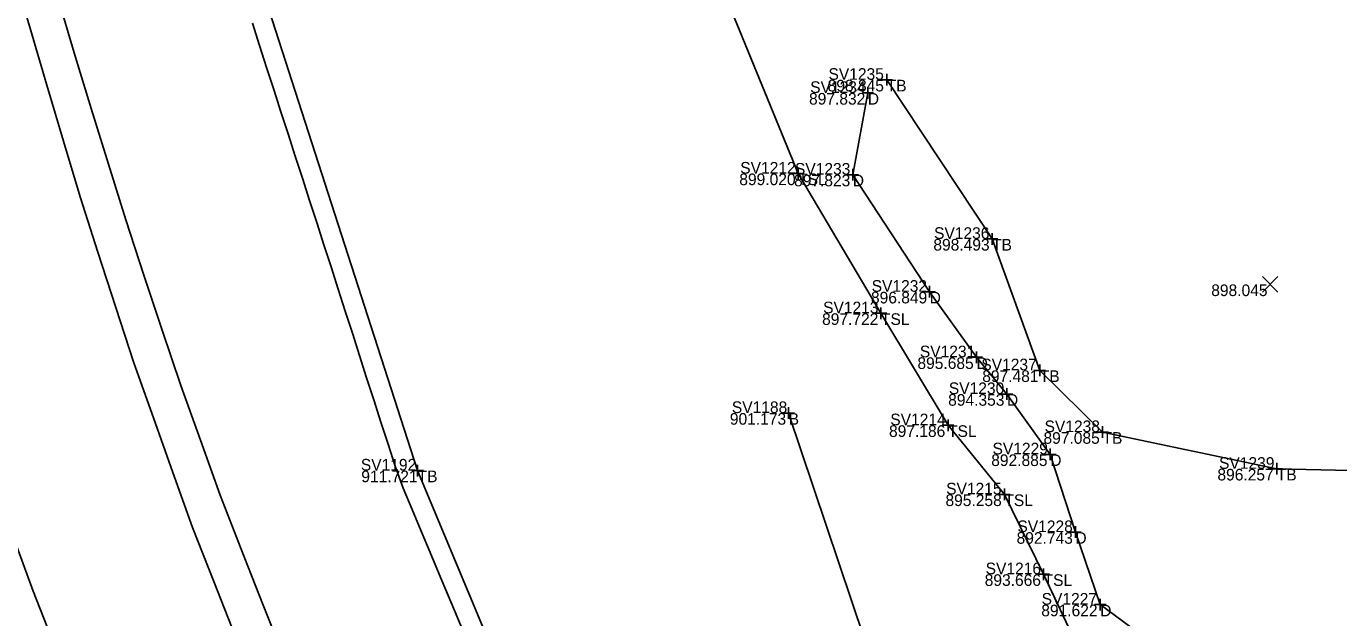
# Model space of a CAD drawing. Extents: x 1918148 to 1919797, y 624701 to 627089.
# Drawn here: x 1918934.8 to 1919047.5, y 625655.4 to 625706.2 of the extents above; entities that cross this region are included whole.
import ezdxf

# ---------------------------------------------------------------- set-up
doc = ezdxf.new("R2010")
doc.units = 0
for name, color, linetype in [('DR_X_Ditch', 7, 'Continuous'), ('PM_X_Edge_Line', 7, 'Continuous'), ('PV_X_Shoulder_Aggregate', 7, 'Continuous'), ('RD_X_Concrete_Pad', 7, 'Continuous'), ('SV_X_Break_Lines', 7, 'Continuous'), ('SV_X_Random_Point', 7, 'Continuous'), ('SV_X_Shot_Marker', 7, 'Continuous'), ('SV_X_Text_Comment', 7, 'Continuous'), ('SV_X_Text_Elevation', 7, 'Continuous'), ('SV_X_Text_Name', 7, 'Continuous'), ('SV_X_Toe_of_Slope', 7, 'Continuous'), ('SV_X_Top_of_Bank', 7, 'Continuous')]:
    doc.layers.add(name, color=color, linetype=linetype)

msp = doc.modelspace()

# ---------------------------------------------------------------- linework, layer by layer
at = {"layer": 'DR_X_Ditch'}
msp.add_lwpolyline([(1919035.48, 625645.33), (1919035.51, 625646.58), (1919031.08, 625653.51), (1919027.02, 625656.51), (1919024.89, 625662.74), (1919022.73, 625669.42), (1919019.01, 625674.6), (1919016.4, 625677.76), (1919012.37, 625683.39), (1919005.77, 625693.45), (1919007.06, 625700.47)], dxfattribs=at)
at = {"layer": 'PM_X_Edge_Line'}
for points in [[(1918933.7, 625710.72), (1918935.12, 625705.92), (1918936.55, 625701.13), (1918937.97, 625696.34), (1918939.4, 625691.55), (1918940.93, 625686.79), (1918942.47, 625682.03), (1918944.02, 625677.28), (1918945.69, 625672.56), (1918947.36, 625667.85), (1918949.05, 625663.15), (1918950.88, 625658.49), (1918952.72, 625653.84)], [(1918933.64, 625662.36), (1918935.37, 625657.67), (1918937.2, 625653.01), (1918939.04, 625648.36), (1918940.88, 625643.72), (1918942.86, 625639.13), (1918944.84, 625634.53), (1918946.83, 625629.94), (1918948.9, 625625.39), (1918950.97, 625620.84), (1918953.05, 625616.3), (1918955.27, 625611.81), (1918957.48, 625607.33), (1918959.71, 625602.86), (1918962.15, 625598.49), (1918964.6, 625594.13), (1918967.05, 625589.77), (1918969.6, 625585.47), (1918972.15, 625581.17)]]:
    msp.add_lwpolyline(points, dxfattribs=at)
at = {"layer": 'PV_X_Shoulder_Aggregate'}
msp.add_lwpolyline([(1918954.19, 625706.47), (1918954.81, 625704.56), (1918955.42, 625702.66), (1918956.04, 625700.76), (1918956.65, 625698.85), (1918957.26, 625696.95), (1918957.88, 625695.05), (1918958.49, 625693.14), (1918959.1, 625691.24), (1918959.72, 625689.33), (1918960.33, 625687.43), (1918960.95, 625685.53), (1918961.56, 625683.62), (1918962.17, 625681.72), (1918962.79, 625679.82), (1918963.4, 625677.91), (1918964.01, 625676.01), (1918964.63, 625674.11), (1918965.24, 625672.2), (1918965.86, 625670.3), (1918966.47, 625668.4), (1918967.16, 625666.52), (1918967.93, 625664.68), (1918968.7, 625662.83), (1918969.47, 625660.98), (1918970.24, 625659.14), (1918971.01, 625657.29), (1918971.78, 625655.45), (1918972.55, 625653.6)], dxfattribs=at)
at = {"layer": 'RD_X_Concrete_Pad'}
msp.add_lwpolyline([(1918937.48, 625708.71), (1918938.89, 625703.91), (1918940.35, 625699.13), (1918941.82, 625694.35), (1918943.32, 625689.58), (1918944.88, 625684.83), (1918946.44, 625680.08), (1918948.06, 625675.35), (1918949.74, 625670.64), (1918951.43, 625665.93), (1918953.22, 625661.27), (1918955.07, 625656.62), (1918956.92, 625651.98)], dxfattribs=at)
at = {"layer": 'SV_X_Break_Lines'}
msp.add_lwpolyline([(1919206.86, 625400.05), (1919170.29, 625439.2), (1919138.05, 625478.01), (1919112.93, 625508.78), (1919087.56, 625546), (1919063.33, 625584.96), (1919048.27, 625604.54), (1919031.79, 625617.49), (1919020.42, 625620.88), (1919013.82, 625627.54), (1919010.2, 625639.42), (1919006.75, 625653.62), (1919000.26, 625672.97)], dxfattribs=at)
at = {"layer": 'SV_X_Random_Point'}
for p, q in [((1919040.96, 625683.35), (1919042.29, 625684.69)), ((1919040.96, 625684.69), (1919042.29, 625683.35))]:
    msp.add_line(p, q, dxfattribs=at)
at = {"layer": 'SV_X_Shot_Marker'}
for p, q in [((1919008.68, 625702.1), (1919008.68, 625701.1)), ((1919007.06, 625700.97), (1919007.06, 625699.97)), ((1919008.18, 625701.6), (1919009.18, 625701.6)), ((1919008.68, 625701.6), (1919008.68, 625701.6)), ((1919006.56, 625700.47), (1919007.56, 625700.47)), ((1919007.06, 625700.47), (1919007.06, 625700.47)), ((1919001.08, 625694.04), (1919001.08, 625693.04)), ((1919005.77, 625693.95), (1919005.77, 625692.95)), ((1919000.58, 625693.54), (1919001.58, 625693.54)), ((1919001.08, 625693.54), (1919001.08, 625693.54)), ((1919005.27, 625693.45), (1919006.27, 625693.45)), ((1919005.77, 625693.45), (1919005.77, 625693.45)), ((1919017.73, 625688.43), (1919017.73, 625687.43)), ((1919017.23, 625687.93), (1919018.23, 625687.93)), ((1919017.73, 625687.93), (1919017.73, 625687.93)), ((1919012.37, 625683.89), (1919012.37, 625682.89)), ((1919011.87, 625683.39), (1919012.87, 625683.39)), ((1919012.37, 625683.39), (1919012.37, 625683.39)), ((1919007.69, 625681.54), (1919008.69, 625681.54)), ((1919008.19, 625682.04), (1919008.19, 625681.04)), ((1919008.19, 625681.54), (1919008.19, 625681.54)), ((1919016.4, 625678.26), (1919016.4, 625677.26)), ((1919015.9, 625677.76), (1919016.9, 625677.76)), ((1919016.4, 625677.76), (1919016.4, 625677.76)), ((1919021.83, 625677.14), (1919021.83, 625676.14)), ((1919021.33, 625676.64), (1919022.33, 625676.64)), ((1919021.83, 625676.64), (1919021.83, 625676.64)), ((1919019.01, 625675.1), (1919019.01, 625674.1)), ((1919018.51, 625674.6), (1919019.51, 625674.6)), ((1919019.01, 625674.6), (1919019.01, 625674.6)), ((1918999.76, 625672.97), (1919000.76, 625672.97)), ((1919000.26, 625673.47), (1919000.26, 625672.47)), ((1919000.26, 625672.97), (1919000.26, 625672.97)), ((1919013.45, 625671.92), (1919014.45, 625671.92)), ((1919013.95, 625672.42), (1919013.95, 625671.42)), ((1919013.95, 625671.92), (1919013.95, 625671.92)), ((1919027.22, 625671.83), (1919027.22, 625670.83)), ((1919026.72, 625671.33), (1919027.72, 625671.33)), ((1919027.22, 625671.33), (1919027.22, 625671.33)), ((1919022.23, 625669.42), (1919023.23, 625669.42)), ((1919022.73, 625669.92), (1919022.73, 625668.92)), ((1919022.73, 625669.42), (1919022.73, 625669.42)), ((1918967.89, 625668.03), (1918968.89, 625668.03)), ((1918968.39, 625668.53), (1918968.39, 625667.53)), ((1918968.39, 625668.03), (1918968.39, 625668.03)), ((1919041.69, 625668.18), (1919042.69, 625668.18)), ((1919042.19, 625668.68), (1919042.19, 625667.68)), ((1919042.19, 625668.18), (1919042.19, 625668.18)), ((1919018.29, 625665.98), (1919019.29, 625665.98)), ((1919018.79, 625666.48), (1919018.79, 625665.48)), ((1919018.79, 625665.98), (1919018.79, 625665.98)), ((1919024.39, 625662.74), (1919025.39, 625662.74)), ((1919024.89, 625663.24), (1919024.89, 625662.24)), ((1919024.89, 625662.74), (1919024.89, 625662.74)), ((1919021.66, 625659.12), (1919022.66, 625659.12)), ((1919022.16, 625659.62), (1919022.16, 625658.62)), ((1919022.16, 625659.12), (1919022.16, 625659.12)), ((1919027.02, 625657.01), (1919027.02, 625656.01)), ((1919026.52, 625656.51), (1919027.52, 625656.51)), ((1919027.02, 625656.51), (1919027.02, 625656.51))]:
    msp.add_line(p, q, dxfattribs=at)
at = {"layer": 'SV_X_Toe_of_Slope'}
msp.add_lwpolyline([(1919144.35, 625769.58), (1919100.27, 625767.87), (1919060.95, 625770.93), (1919021.62, 625778.27), (1918998.32, 625779.77), (1918985.02, 625778.23), (1918981.12, 625762.93), (1918979.64, 625746.6), (1918992.24, 625715.18), (1919001.08, 625693.54), (1919008.19, 625681.54), (1919013.95, 625671.92), (1919018.79, 625665.98), (1919022.16, 625659.12), (1919025.26, 625652.5), (1919028.92, 625643.15)], dxfattribs=at)
at = {"layer": 'SV_X_Top_of_Bank'}
for points in [[(1919180.03, 625377.77), (1919142.39, 625420.85), (1919113.9, 625458.17), (1919086.6, 625489.42), (1919057.39, 625523.08), (1919019.76, 625570.22), (1918998.07, 625602.27), (1918985.26, 625627.56), (1918968.39, 625668.03), (1918955.62, 625707.63), (1918947.9, 625739.17), (1918945.04, 625765.59), (1918947.37, 625785.94), (1918957.93, 625802.75), (1918975.61, 625809.21), (1918997.58, 625813.39), (1919030.67, 625814.44), (1919065.45, 625812.35), (1919111.29, 625808.54)], [(1919008.68, 625701.6), (1919017.73, 625687.93), (1919021.83, 625676.64), (1919027.22, 625671.33), (1919042.19, 625668.18), (1919068.63, 625667.59), (1919096.2, 625663.51), (1919124.68, 625660.31), (1919151.38, 625658.36), (1919165.45, 625659.92), (1919167.97, 625668.32), (1919163.99, 625682.32), (1919158.88, 625699.33), (1919157.69, 625715.48), (1919158.89, 625735.48)]]:
    msp.add_lwpolyline(points, dxfattribs=at)

# ---------------------------------------------------------------- texts
at = {"layer": 'SV_X_Text_Comment'}
for s, p in [('TB', (1919008.68, 625700.6)), ('D', (1919007.06, 625699.47)), ('TSL', (1919001.08, 625692.55)), ('D', (1919005.77, 625692.45)), ('TB', (1919017.73, 625686.93)), ('D', (1919012.37, 625682.39)), ('TSL', (1919008.19, 625680.54)), ('D', (1919016.4, 625676.76)), ('TB', (1919021.83, 625675.64)), ('D', (1919019.01, 625673.6)), ('B', (1919000.26, 625671.97)), ('TSL', (1919013.95, 625670.92)), ('TB', (1919027.22, 625670.33)), ('D', (1919022.73, 625668.42)), ('TB', (1918968.39, 625667.03)), ('TB', (1919042.19, 625667.18)), ('TSL', (1919018.79, 625664.98)), ('D', (1919024.89, 625661.74)), ('TSL', (1919022.16, 625658.12)), ('D', (1919027.02, 625655.51))]:
    msp.add_text(s, height=1, dxfattribs=at).set_placement(p)
at = {"layer": 'SV_X_Text_Elevation'}
for s, p in [('898.845', (1919003.61, 625700.6)), ('897.832', (1919002.01, 625699.47)), ('899.020', (1918996.02, 625692.55)), ('897.823', (1919000.72, 625692.45)), ('898.493', (1919012.69, 625686.93)), ('898.045', (1919036.56, 625683.02)), ('896.849', (1919007.33, 625682.39)), ('897.722', (1919003.13, 625680.54)), ('895.685', (1919011.32, 625676.76)), ('897.481', (1919016.89, 625675.64)), ('894.353', (1919013.96, 625673.6)), ('901.173', (1918995.21, 625671.97)), ('897.186', (1919008.88, 625670.92)), ('897.085', (1919022.15, 625670.33)), ('892.885', (1919017.66, 625668.42)), ('911.721', (1918963.55, 625667.03)), ('896.257', (1919037.09, 625667.18)), ('895.258', (1919013.73, 625664.98)), ('892.743', (1919019.84, 625661.74)), ('893.666', (1919017.1, 625658.12)), ('891.622', (1919021.96, 625655.51))]:
    msp.add_text(s, height=1, dxfattribs=at).set_placement(p)
at = {"layer": 'SV_X_Text_Name'}
for s, p in [('SV1235', (1919003.68, 625701.6)), ('SV1234', (1919002.11, 625700.47)), ('SV1212', (1918996.1, 625693.54)), ('SV1233', (1919000.8, 625693.45)), ('SV1236', (1919012.75, 625687.93)), ('SV1232', (1919007.39, 625683.39)), ('SV1213', (1919003.22, 625681.54)), ('SV1231', (1919011.53, 625677.76)), ('SV1237', (1919016.81, 625676.64)), ('SV1230', (1919014.02, 625674.6)), ('SV1188', (1918995.38, 625672.97)), ('SV1214', (1919008.99, 625671.92)), ('SV1238', (1919022.24, 625671.33)), ('SV1229', (1919017.77, 625669.42)), ('SV1239', (1919037.23, 625668.18)), ('SV1192', (1918963.51, 625668.03)), ('SV1215', (1919013.79, 625665.98)), ('SV1228', (1919019.91, 625662.74)), ('SV1216', (1919017.18, 625659.12)), ('SV1227', (1919021.99, 625656.51))]:
    msp.add_text(s, height=1, dxfattribs=at).set_placement(p)

doc.saveas('drawing.dxf')
